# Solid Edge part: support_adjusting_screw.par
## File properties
Title: Support adjusting screw
Author: Robert a Rhodes jr
Template: Normal.par
Last saved by: SOFT
Revision: 15
Application: Solid Edge
Accuracy: 0.99
Material: aluminum
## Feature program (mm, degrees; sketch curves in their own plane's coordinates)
sketch for "unnamed Protrusion 1" plane through (0, 0, 0) normal (0, -1, 0) x-axis (1, 0, 0)
  circle centre (0, 0) radius 38.1
extrude "unnamed Protrusion 1" add finite 584.2 along +normal
sketch for "ExtrudedCutout_1" plane through (0, -521.208, 0) normal (0, -1, 0) x-axis (1, 0, 0)
extrude "ExtrudedCutout_1" cut finite 76.2 along +normal  Plane_Distance = 62.992 mm
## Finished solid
Body 1: solid body, 5 faces, 4 edges, 0 vertices.
  Faces by surface: plane 3, cylinder 2
  Edges by curve: circle 4
Bounding box of the edges (mm): 76.200 x 584.200 x 76.200, from (-38.1, -584.2, -38.1) to (38.1, 0, 38.1).
Cylindrical faces by radius (mm): R25.4 x1, R38.1 x1
Planar faces by outward normal: +y 1, -y 2
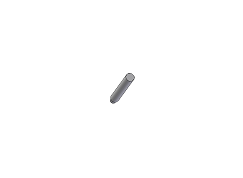
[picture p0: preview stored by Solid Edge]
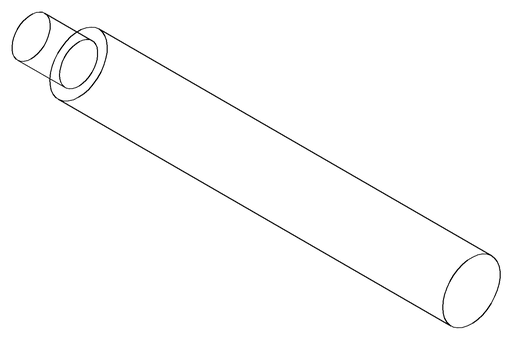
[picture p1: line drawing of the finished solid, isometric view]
